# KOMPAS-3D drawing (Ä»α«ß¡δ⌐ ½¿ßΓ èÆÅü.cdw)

Views: Вид транспорта
Referenced files: Опросник.cdw
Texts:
  ОВВО
  ЗАО "ЧЭАЗ"
  Текст на чертеже
  Размерные надписи
  Шероховатость
  Линия-выноска #1
  Линия-выноска #2
  Линия-выноска #3
  Отклонения формы и база
  Заголовок таблицы
  Ячейка таблицы
  Стрелка вида
  Обозначение изменения
  Фигурная скобка
  Номер узла
  Марка координационной оси
  VRCB
  Выносная надпись
  Обозначение узла
  Марка/позиционное обозначение с линией-выноской
  Марка/позиционное обозначение на линии
  Марка/позиционное обозначение без линии-выноски
  Normal
  Лит-Масса-Масштаб
  Материал-Предприятие
  Обычный+1
  Тип КТПБ
  Очередь поставки
  № чертежа опросного листа на
  Номинальный ток ввода КРУ (КРУН) 10(6)кВ,  А
  Тип разъединителя
  Тип выключателя
  Тип трансформатора тока
  Тип трансформатора напряжения
  Тип ограничителя перенапряжения
  Тип аппарата защиты нейтрали обмоток
  ВН силового трансформатора
  Количество обрабатываемых фаз
  В.Ч. связи
  Тип силового трансформатора
  Тип трансформатора собственных нужд
  Блок В.Ч. связи 110 кВ для третьей фазы
  Прожекторные мачты, шт
  Порталы, шт
  Внешнее ограждение подстанции, п.м.
  Молниеотводы, шт
  Шумозащитное ограждение, п.м.
  Технические
  параметры
  блоков 35 кВ
  блоков 110 кВ
  КРУ 10(6)
  КРУН 10(6)
  ОПУ
  наружный
  внутренний
  ПМС
  ПС-35
  ПСЛ-110
  Назначение блоков 35 кВ
  Обозначение блока 35 кВ
  Схема вспом. соединений блока
  Коэф. трансформации
  трансф. тока 35 кВ
  Исполнение привода
  выносных
  встроенных
  выключателя
  разъединителя
  Номинальный ток, А
  Ток термической стойкости, кА
  Номинальный ток сборных шин, А
  Номинальное напряжение цепей
  управления приводом выключателя
  Номинальное напряжение электро-
  двигателя привода выключателя
  Обозначение блока 110 кВ
  трансф. тока 110 кВ
  ПСТ-110
  ПМЖ
  Иные:
  СОГЛАСОВАНО
  УТВЕРЖДАЮ ЗАКАЗЧИК
  УТВЕРЖДАЮ ПРОЕКТНЫЙ ИНСТИТУТ
  Дополнительные технические требования:
  Примечания:
  Опросной лист  КТПБ   ЗАО "ЧЭАЗ"
Dimensions and other numbers on the sheet: 7; 1; 2; 3; 4; 5; 6; 8; 9; 10; 11; 12; 13; 14; 15; 17; 16; 18; 19; 20; 21; 35 кВ; 110 кВ; 68; 0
